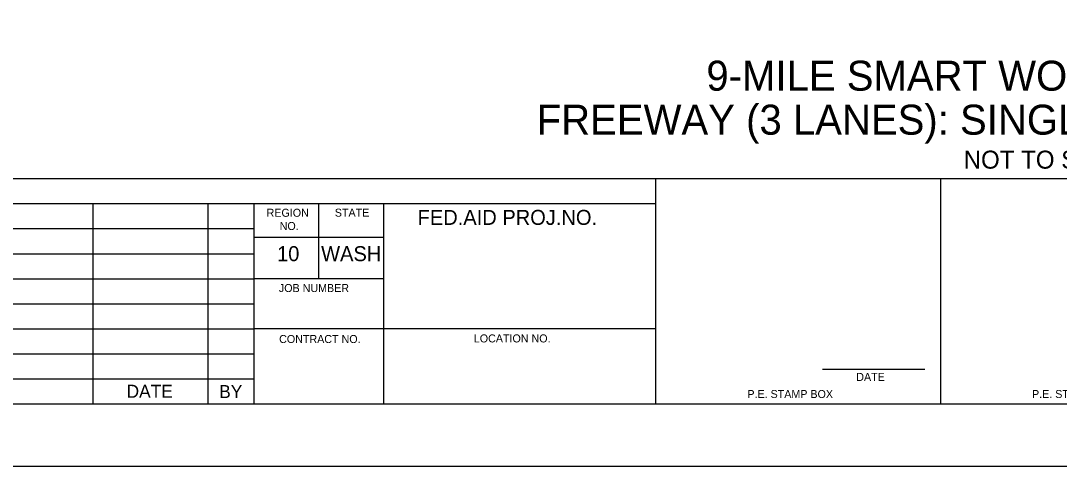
# Model space of a CAD drawing. Extents: x 99999.1 to 100055.7, y 99995 to 100017.5.
# Drawn here: x 100004.28 to 100009.47, y 99999.69 to 100001.92 of the extents above; entities that cross this region are included whole.
import ezdxf

# ---------------------------------------------------------------- set-up
doc = ezdxf.new("R2010")
doc.units = 0
for name, color, linetype in [('SH_DE_DetailHeading1Text', 7, 'Continuous'), ('SH_DE_DetailHeading3Text', 7, 'Continuous'), ('SH_GI_PlotLimits', 7, 'Continuous'), ('SH_GI_SheetBorder', 7, 'Continuous'), ('SH_GI_SheetTextInCells', 7, 'Continuous')]:
    doc.layers.add(name, color=color, linetype=linetype)

msp = doc.modelspace()

# ---------------------------------------------------------------- linework, layer by layer
at = {"layer": 'SH_GI_PlotLimits'}
msp.add_lwpolyline([(99999.0625, 99999.6875), (100016.0625, 99999.6875), (100016.0625, 100010.6875), (99999.0625, 100010.6875)], close=True, dxfattribs=at)
at = {"layer": 'SH_GI_SheetBorder'}
for p, q in [((100000, 100001.1259), (100015.75, 100001.1259)), ((100007.4566, 100000), (100007.4566, 100001.1259)), ((100008.8828, 100000), (100008.8828, 100001.1259)), ((100000, 100001.0008), (100007.4566, 100001.0008)), ((100004.641, 100001.0008), (100004.641, 100000)), ((100005.2164, 100001.0008), (100005.2164, 100000)), ((100005.4451, 100001.0008), (100005.4451, 100000)), ((100005.7719, 100000.6255), (100005.7719, 100001.0008)), ((100006.0956, 100000), (100006.0956, 100001.0008)), ((100002.1821, 100000.8757), (100005.4466, 100000.8757)), ((100006.0958, 100000.831), (100005.4466, 100000.831)), ((100002.1821, 100000.7506), (100005.4466, 100000.7506)), ((100000, 100000.6255), (100005.4466, 100000.6255)), ((100006.0958, 100000.6255), (100005.4466, 100000.6255)), ((100000, 100000.5004), (100005.4466, 100000.5004)), ((100000, 100000.3753), (100005.4466, 100000.3753)), ((100007.4566, 100000.3753), (100005.4466, 100000.3753)), ((100000, 100000.2502), (100005.4466, 100000.2502)), ((100008.2903, 100000.1733), (100008.802, 100000.1733)), ((100000, 100000.1251), (100005.4466, 100000.1251)), ((100000, 100000), (100015.75, 100000))]:
    msp.add_line(p, q, dxfattribs=at)

# ---------------------------------------------------------------- texts
at = {"layer": 'SH_DE_DetailHeading1Text'}
for s, p in [('9-MILE SMART WORK ZONE SYSTEM', (100007.7097, 100001.5658)), ('FREEWAY (3 LANES): SINGLE RIGHT LANE CLOSURE', (100006.8609, 100001.3458))]:
    msp.add_text(s, height=0.15, dxfattribs=at).set_placement(p)
at = {"layer": 'SH_DE_DetailHeading3Text'}
msp.add_text('NOT TO SCALE', height=0.09, dxfattribs=at).set_placement((100008.9969, 100001.1759))
at = {"layer": 'SH_GI_SheetTextInCells'}
for s, height, p in [('REGION', 0.04003, (100005.5099, 100000.9352)), ('STATE', 0.04003, (100005.8511, 100000.9357)), ('FED.AID PROJ.NO.', 0.07506, (100006.2652, 100000.8945)), ('NO.', 0.04003, (100005.5752, 100000.869)), ('10', 0.07506, (100005.5621, 100000.7131)), ('WASH', 0.07506, (100005.7826, 100000.7131)), ('JOB NUMBER', 0.04003, (100005.5712, 100000.5587)), ('CONTRACT NO.', 0.040032, (100005.5725, 100000.3037)), ('LOCATION NO.', 0.040032, (100006.5465, 100000.3067)), ('DATE', 0.04003, (100008.4597, 100000.1141)), ('DATE', 0.06505, (100004.8091, 100000.03)), ('BY', 0.06505, (100005.2725, 100000.0285)), ('P.E. STAMP BOX', 0.040032, (100007.915, 100000.0286)), ('P.E. STAMP BOX', 0.040032, (100009.339, 100000.0286))]:
    msp.add_text(s, height=height, dxfattribs=at).set_placement(p)

doc.saveas('drawing.dxf')
